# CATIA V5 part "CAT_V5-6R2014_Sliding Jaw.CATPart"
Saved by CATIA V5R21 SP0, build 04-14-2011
Part number: Sliding Jaw
Bounding box of the stored display mesh (mm): x -32 to 32, y -16 to 16, z -9 to 36
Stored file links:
  D:\CATIA V5R21 E-RESOURCES\CATIA-V5R21\catia-v5r21-prt\c16-catia-v5r20-prt\c16-catia-v5r21-tut01\CAT_V5R21_Sliding Jaw.CATPart
  C:\Program Files\Dassault Systemes\B09\intel_a\reffiles\standard\MetricThickPitch.txt
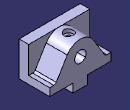
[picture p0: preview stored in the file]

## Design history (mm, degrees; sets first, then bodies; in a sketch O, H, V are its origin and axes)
Body1 (main body)
  Sketch1 on xy-plane, origin (0, 0, 0), H (1, 0, 0), V (0, 1, 0)
    line L1 (-32, -16) -> (32, -16)
    line L2 (32, -16) -> (32, 16)
    line L3 (32, 16) -> (-32, 16)
    line L4 (-32, 16) -> (-32, -16)
    distance H L1 = 16
    distance V L4 = 32
    length L4 = 32
    length L1 = 64
    horizontal: L1 H, L3 H
    vertical: L2 V, L4 V
  Pad1: profile Sketch1, direction (0, 0, 1), length 8
  Sketch2 on face of Pad1, origin (0, -16, 0), H (1, 0, 0), V (0, 0, 1)
    point P1 (-32, 0)
    line L1 (-32, 0) -> (32, 0)
    line L2 (32, 0) -> (32, 36)
    line L3 (32, 36) -> (-32, 36)
    line L4 (-32, 36) -> (-32, 0)
    reference projected line E1 (32, 0) -> (32, 8) from edge of Pad1
    reference projected line E2 (-32, 8) -> (-32, 0) from edge of Pad1
    length L2 = 36
    coincidence: P1 H, L2 E1, L4 E2
    horizontal: L1 H, L3 H
    vertical: L2 V, L4 V
  Pad2: profile Sketch2, direction (0, 1, 0), length 10
  Sketch3 on face of Pad1, origin (0, 16, 0), H (-1, 0, 0), V (0, 0, 1)
    arc A1 centre (0, 20) radius 16 from (13.6777, 28.3018) to (-13.6777, 28.3018) ccw
    point P1 (0, 20)
    reference projected line E1 (-32, 36) -> (32, 36) from edge of Pad2
    line L1 (-26, 8) -> (-13.6777, 28.3018)
    point P2 (-26, 8)
    line L2 (13.6777, 28.3018) -> (26, 8)
    point P3 (26, 8)
    reference projected line E2 (32, 8) -> (-32, 8) from edge of Pad1
    reference projected line E3 (32, 8) -> (-32, 8) from edge of Pad1
    line L3 (-26, 8) -> (26, 8)
    radius A1 = 16
    length L3 = 52
    distance V P3 = 26
    coincidence: P1 V, E2 P2, E3 P3
    tangency: A1 E1, L2 A1, L1 A1
    horizontal: L3 H
  Pad3: profile Sketch3, direction (0, -1, 0), up to the existing solid (limit type 2)
  Fillet1: radius 3, on 2 edges
  Sketch4 on face of Pad1, origin (-2.6964, 16, 22.8197), H (1, 0, 0), V (0, 0, -1)
    point P1 (2.6964, 2.8197)
    reference projected arc E1 centre (2.6964, 2.8197) radius 16 from (-10.9814, -5.4821) to (16.3741, -5.4821) ccw from edge of Pad3
    concentricity: P1 E1
  Hole1: placed by Sketch4, at (0, 16, 20) direction (0, -1, 0), diameter 12, depth 22, V-bottom angle 120
  Sketch5 on face of Pad1, origin (0, 16, 0), H (-1, 0, 0), V (0, 0, 1)
    point P1 (-7.75, 0)
    line L1 (-7.75, 0) -> (7.75, 0)
    line L2 (7.75, 0) -> (7.75, -9)
    line L3 (7.75, -9) -> (-7.75, -9)
    line L4 (-7.75, -9) -> (-7.75, 0)
    distance V L2 = 7.75
    length L3 = 15.5
    length L4 = 9
    coincidence: P1 H
    horizontal: L1 H, L3 H
    vertical: L2 V, L4 V
  Pad4: profile Sketch5, direction (0, -1, 0), length 32
  Sketch6 on face of Pad4, origin (-0.598, -1.2346, -9), H (1, 0, 0), V (0, -1, 0)
    point P1 (0.598, -9.2346)
    reference projected line E1 (8.348, -17.2346) -> (-7.152, -17.2346) from edge of Pad4
    reference projected line E2 (8.348, 14.7654) -> (8.348, -17.2346) from edge of Pad4
    distance P1 E1 = 8
    distance P1 E2 = 7.75
  Hole2: placed by Sketch6, at (0, 8, -9) direction (0, 0, 1), diameter 5, depth 16, V-bottom angle 120, threaded, thread diameter 6, thread depth 16, pitch 1
  RectPattern1: of Hole2, direction 1 instances 2, spacing 16, along edge of Pad4 reversed
  Sketch7 on face of Pad2, origin (-19.6018, -13.7351, 36), H (1, 0, 0), V (0, 1, 0)
    point P1 (19.6018, 17.7351)
    reference intersected line E1 through (19.6018, 0) direction (0, 1) from yz-plane
    reference projected line E2 (51.6018, -2.2649) -> (-12.3982, -2.2649) from edge of Pad2
    distance P1 E2 = 20
    coincidence: E1 P1
  Hole3: placed by Sketch7, at (0, 4, 36) direction (0, 0, -1), diameter 5, depth 16, V-bottom angle 120, counterbore diameter 10, counterbore depth 4, threaded, thread diameter 6, thread depth 11, pitch 1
